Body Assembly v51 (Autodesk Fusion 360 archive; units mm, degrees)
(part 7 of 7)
sketch "Sketch1" plane through (0, 0, 0) normal (0, 0, 1) x axis (1, 0, 0)
  line L1 (-7.25, -8.75) -> (7.25, -8.75)
  line L2 (-7.25, 8.75) -> (-7.25, -8.75)
  line L3 (7.25, 8.75) -> (-7.25, 8.75)
  line L4 (7.25, -8.75) -> (7.25, 8.75)
  line L5 (-7.25, 8.75) -> (7.25, -8.75)
  line L6 (7.25, 8.75) -> (-7.25, -8.75)
  line L7 (0, 8.75) -> (0, -8.75)
  line L8 (-2.5, -2.35) -> (2.5, -2.35)
  line L9 (-2.5, 1.45) -> (-2.5, -2.35)
  line L10 (2.5, 1.45) -> (-2.5, 1.45)
  line L11 (2.5, -2.35) -> (2.5, 1.45)
  line L12 (-2.5, 1.45) -> (2.5, -2.35)
  line L13 (2.5, 1.45) -> (-2.5, -2.35)
  line L14 (7.25, -0.45) -> (-7.25, -0.45)
  line L15 (3.75, -8.75) -> (7.25, -5.25)
  line L16 (-3.75, -8.75) -> (-7.25, -5.25)
  arc A1 centre (0, 0.1797) radius 8.5703 clockwise from (-7.25, 4.75) to (7.25, 4.75)
  circle C1 centre (6, -0.45) radius 1.5
  circle C2 centre (-6, -0.45) radius 1.5
  point P6 (0, 0)
  point P1 (0, 0)
  point P7 (0, -8.75)
  point P8 (0, 8.75)
  point P13 (0, -0.45)
  point P14 (-7.25, -0.45)
  point P15 (7.25, -0.45)
  point P16 (7.25, 4.75)
  point P17 (-7.25, 4.75)
  point P19 (7.25, 4.75)
  point P18 (-7.25, 4.75)
  point P21 (7.25, -5.25)
  point P22 (3.75, -8.75)
  point P23 (7.25, -5.25)
  point P24 (3.75, -8.75)
  point P25 (-7.25, -5.25)
  point P26 (-3.75, -8.75)
  point P27 (6, -0.45)
  point P2 (7.25, -8.75)
  point P5 (7.25, 8.75)
  horizontal L1
  perpendicular L1 L2
  parallel L1 L3
  parallel L2 L4
  coincident L5 P6
  coincident L6 P6
  coincident P1 P6
  midpoint L1 P7
  midpoint L3 P8
  horizontal L8
  perpendicular L8 L9
  parallel L8 L10
  parallel L9 L11
  coincident L12 P13
  coincident L13 P13
  coincident L7 P13
  coincident L2 P14
  coincident L4 P15
  perpendicular L4 L14
  coincident P13 L14
  coincident L4 P16
  symmetric L7 P16 P17
  coincident P8 A1
  tangent L3 A1
  coincident P16 P19
  coincident P17 P18
  coincident L4 P21
  coincident L1 P22
  coincident P21 P23
  coincident P22 P24
  symmetric L7 P23 P25
  symmetric L7 P24 P26
  coincident L14 P27
  symmetric L7 C1 C2
  dimension "d1_4" distance P2 P5 = 17.5
  dimension "d2_4" distance L2 L4 = 14.5
  dimension "d3_4" distance L1 L8 = 6.4
  dimension "d4_4" distance L3 L10 = 7.3
  dimension "d5_4" distance L9 L11 = 5
  dimension "d6_4" distance P5 P16 = 4
  dimension "d7_4" distance P2 P21 = 3.5
  dimension "d8_4" distance P2 P22 = 3.5
  dimension "d9_4" diameter C1 = 3
  dimension "d10_4" distance L11 P27 = 3.5 (= "2 mm + 1.5 mm")
extrude "Extrude1" new body sketch "Sketch1" profile of L1 L2 L4 L8 L9 L10 L11 A1 L15 L16 C1 C2 against normal blind 1.7 named "d11_4"
extrude "Extrude2" new body sketch "Sketch1" profile of L8 L9 L10 L11 along normal blind 1.5 named "d13_4"
sketch "Sketch2" plane through (0, 0, 0) normal (0, 0, 1) x axis (-1, 0, 0)
  line L1 (3.75, 8.75) -> (7.25, 5.25)
  line L2 (-3.75, 8.75) -> (3.75, 8.75)
  line L3 (-7.25, 5.25) -> (-3.75, 8.75)
  line L4 (-7.25, 1.2792) -> (-7.25, 5.25)
  line L5 (-7.25, -4.75) -> (-7.25, -0.3792)
  line L6 (7.25, -0.3792) -> (7.25, -4.75)
  line L7 (7.25, 5.25) -> (7.25, 1.2792)
  line L8 (2.5, -1.45) -> (-2.5, -1.45)
  line L9 (2.5, 2.35) -> (2.5, -1.45)
  line L10 (-2.5, 2.35) -> (2.5, 2.35)
  line L11 (-2.5, -1.45) -> (-2.5, 2.35)
  line L12 (2.5, 2.35) -> (-2.5, -1.45)
  line L13 (2.5, -1.45) -> (-2.5, 2.35)
  line L14 (11.5, 11.95) -> (-11.5, 11.95)
  line L15 (11.5, -11.05) -> (11.5, 11.95)
  line L16 (-11.5, -11.05) -> (11.5, -11.05)
  line L17 (-11.5, 11.95) -> (-11.5, -11.05)
  line L18 (11.5, -11.05) -> (-11.5, 11.95)
  line L19 (-11.5, -11.05) -> (11.5, 11.95)
  line L20 (8.5, 8.95) -> (-8.5, 8.95)
  line L21 (8.5, -8.05) -> (8.5, 8.95)
  line L22 (-8.5, -8.05) -> (8.5, -8.05)
  line L23 (-8.5, 8.95) -> (-8.5, -8.05)
  line L24 (8.5, -8.05) -> (-8.5, 8.95)
  line L25 (-8.5, -8.05) -> (8.5, 8.95)
  arc A1 centre (-6, 0.45) radius 1.5 clockwise from (-7.25, 1.2792) to (-7.25, -0.3792)
  arc A2 centre (0, -0.1797) radius 8.5703 clockwise from (7.25, -4.75) to (-7.25, -4.75)
  arc A3 centre (6, 0.45) radius 1.5 clockwise from (7.25, -0.3792) to (7.25, 1.2792)
  circle C1 centre (-8.5, 8.95) radius 1.5
  point P15 (-2.5, -1.45)
  point P19 (-2.5, -1.45)
  point P17 (2.5, 2.35)
  point P20 (2.5, 2.35)
  point P18 (-2.5, 2.35)
  point P21 (-2.5, 2.35)
  point P16 (2.5, -1.45)
  point P22 (2.5, -1.45)
  point P27 (0, 0.45)
  point P32 (0, 0.45)
  point P28 (-8.5, 8.95)
  point P33 (-8.5, 8.95)
  point P25 (11.5, -11.05)
  point P26 (-11.5, -11.05)
  point P24 (11.5, 11.95)
  point P29 (8.5, 8.95)
  point P31 (-8.5, -8.05)
  coincident P15 P19
  coincident P17 P20
  coincident P18 P21
  coincident P16 P22
  horizontal L14
  perpendicular L14 L15
  parallel L14 L16
  parallel L15 L17
  coincident L18 P27
  coincident L19 P27
  midpoint L12 P27
  horizontal L20
  perpendicular L20 L21
  parallel L20 L22
  parallel L21 L23
  coincident L24 P32
  coincident L25 P32
  coincident P27 P32
  coincident P28 P33
  dimension "d15_3" distance P25 P26 = 23
  dimension "d16_3" distance P24 P25 = 23
  dimension "d21_3" distance P28 P29 = 17
  dimension "d22_1" distance P28 P31 = 17
  dimension "d23_1" diameter C1 = 3
extrude "Extrude3" add sketch "Sketch2" profile of L1 L2 L3 L4 A1 L5 A2 L6 A3 L7 L8 L9 L10 L11 L14 L15 L16 L17 against normal blind 1.7 named "d17_3"
fillet "Fillet1" radius 3 named "d20_3"
extrude "Extrude4" cut sketch "Sketch2" profile of C1 against normal blind 5 named "d24_1"
work_axis "WorkAxis1" sketch "Sketch2"
circular_pattern "C-Pattern1" TotalAngle 360 named "d27_1"
copy_paste "CutPaste7"
copy_paste_bodies "CopyPasteBodies1"
component_from_bodies "Body->Comp2"
copy_paste "CutPaste1"
sketch "Sketch26" plane through (0, 0, 3.1168) normal (0, 0, 1) x axis (-1, 0, 0)
  line L1 (-17.255, -17.7958) -> (-17.255, -11.4458)
  line L2 (-3.4928, -22.1208) -> (-13.668, -22.1208)
  line L3 (0.1537, -18.4744) -> (-3.4928, -22.1208)
  line L4 (0.1537, -10.7673) -> (0.1537, -18.4744)
  line L5 (-3.4928, -7.1208) -> (0.1537, -10.7673)
  line L6 (-13.668, -7.1208) -> (-3.4928, -7.1208)
  line L7 (-10.2963, -17.1208) -> (-10.2963, -12.1208)
  line L8 (-6.4963, -17.1208) -> (-10.2963, -17.1208)
  line L9 (-6.4963, -12.1208) -> (-6.4963, -17.1208)
  line L10 (-10.2963, -12.1208) -> (-6.4963, -12.1208)
  line L11 (-6.4963, -12.1208) -> (-10.2963, -17.1208)
  line L12 (-10.2963, -12.1208) -> (-6.4963, -17.1208)
  line L13 (6.8437, -26.1208) -> (-23.6363, -26.1208)
  line L14 (6.8437, -3.1208) -> (6.8437, -26.1208)
  line L15 (-23.6363, -3.1208) -> (6.8437, -3.1208)
  line L16 (-23.6363, -26.1208) -> (-23.6363, -3.1208)
  line L17 (6.8437, -3.1208) -> (-23.6363, -26.1208)
  line L18 (-23.6363, -3.1208) -> (6.8437, -26.1208)
  line L19 (-23.8863, -26.3708) -> (-23.8863, -2.8708)
  line L20 (7.0937, -26.3708) -> (-23.8863, -26.3708)
  line L21 (7.0937, -2.8708) -> (7.0937, -26.3708)
  line L22 (-23.8863, -2.8708) -> (7.0937, -2.8708)
  line L23 (-3.6338, -9.3883) -> (-13.1588, -9.3883)
  line L24 (-3.6338, 21.6466) -> (-3.6338, -9.3883)
  line L25 (-13.1588, 21.6466) -> (-3.6338, 21.6466)
  line L26 (-13.1588, -9.3883) -> (-13.1588, 21.6466)
  line L27 (-3.6338, 21.6466) -> (-13.1588, -9.3883)
  line L28 (-13.1588, 21.6466) -> (-3.6338, -9.3883)
  line L29 (-2.7026, -22.1208) -> (-4.2901, -22.1208)
  line L30 (-2.7026, -36.2208) -> (-2.7026, -22.1208)
  line L31 (-4.2901, -36.2208) -> (-2.7026, -36.2208)
  line L32 (-4.2901, -22.1208) -> (-4.2901, -36.2208)
  line L33 (-2.7026, -36.2208) -> (-4.2901, -22.1208)
  line L34 (-4.2901, -36.2208) -> (-2.7026, -22.1208)
  line L35 (-12.5026, -24.395) -> (-14.0901, -24.395)
  line L36 (-12.5026, -33.9467) -> (-12.5026, -24.395)
  line L37 (-14.0901, -33.9467) -> (-12.5026, -33.9467)
  line L38 (-14.0901, -24.395) -> (-14.0901, -33.9467)
  line L39 (-12.5026, -33.9467) -> (-14.0901, -24.395)
  line L40 (-14.0901, -33.9467) -> (-12.5026, -24.395)
  arc A1 centre (-9.026, -14.6208) radius 8.8203 clockwise from (-13.668, -22.1208) to (-17.255, -17.7958)
  arc A2 centre (-9.026, -14.6208) radius 8.8203 clockwise from (-17.255, -11.4458) to (-13.668, -7.1208)
  circle C1 centre (-3.4963, -29.1708) radius 2.2
  arc A3 centre (-8.3963, 6.1292) radius 8.75 clockwise from (-16.55, 9.3042) to (-16.55, 2.9542)
  circle C2 centre (-13.2963, -29.1708) radius 2.2
  point P12 (-10.2963, -17.1208)
  point P15 (-10.2963, -17.1208)
  point P14 (-6.4963, -12.1208)
  point P16 (-6.4963, -12.1208)
  point P13 (-6.4963, -17.1208)
  point P17 (-6.4963, -17.1208)
  point P11 (-10.2963, -12.1208)
  point P18 (-10.2963, -12.1208)
  point P19 (-8.3963, -14.6208)
  point P24 (-8.3963, -14.6208)
  point P37 (-8.3963, 6.1292)
  point P32 (-8.3963, 6.1292)
  point P38 (-4.2901, -22.1208)
  point P42 (-3.4963, -29.1708)
  point P25 (-3.4963, -29.1708)
  point P48 (-13.2963, -29.1708)
  point P43 (-13.2963, -29.1708)
  point P21 (6.8437, -26.1208)
  point P22 (6.8437, -3.1208)
  point P20 (-23.6363, -26.1208)
  point P33 (-13.1588, -9.3883)
  point P34 (-3.6338, -9.3883)
  point P46 (-12.5026, -33.9467)
  point P47 (-14.0901, -33.9467)
  point P40 (-2.7026, -36.2208)
  point P41 (-4.2901, -36.2208)
  coincident P12 P15
  coincident P14 P16
  coincident P13 P17
  coincident P11 P18
  midpoint L12 P19
  horizontal L13
  perpendicular L13 L14
  parallel L13 L15
  parallel L14 L16
  coincident L17 P24
  coincident L18 P24
  coincident P19 P24
  horizontal L23
  perpendicular L23 L24
  parallel L23 L25
  parallel L24 L26
  coincident L27 P37
  coincident L28 P37
  coincident P32 P37
  horizontal L29
  perpendicular L29 L30
  parallel L29 L31
  parallel L30 L32
  coincident L2 P38
  coincident L33 P42
  coincident L34 P42
  coincident P25 P42
  horizontal L35
  perpendicular L35 L36
  parallel L35 L37
  parallel L36 L38
  coincident L39 P48
  coincident L40 P48
  coincident P43 P48
  dimension "d229" distance P21 P22 = 23
  dimension "d230" distance P20 P21 = 30.48
  dimension "d231" = 0.25
  dimension "d232" distance P33 P34 = 9.525
  dimension "d235" distance P46 P47 = 1.5875 (= "( 1 / 16 ) * 1 in")
  dimension "d236" distance P40 P41 = 1.5875 (= "( 1 / 16 ) * 1 in")
extrude "Extrude1" cut sketch "Sketch26" profile of L1 A1 L2 L3 L4 L5 L6 A2 C1 L19 L20 L21 L22 A3 L23 L24 L26 L29 L30 L32 C2 L35 L36 L38 along normal blind 11.43
position "Position9"
extrude "Extrude2" add of existing geometry blind 11.938
copy_paste "CutPaste1"
copy_paste "CutPaste2"
sketch "Sketch27" plane through (0, 0, 8.3168) normal (0, 0, 1) x axis (-1, 0, 0)
  line L1 (-1.5476, 25.3604) -> (3.2149, 20.5979)
  line L2 (-15.2451, 25.3604) -> (-1.5476, 25.3604)
  line L3 (-20.0076, 20.5979) -> (-15.2451, 25.3604)
  line L4 (-20.0076, 9.3042) -> (-20.0076, 20.5979)
  line L5 (-16.55, 9.3042) -> (-20.0076, 9.3042)
  line L6 (-20.0076, 2.9542) -> (-16.55, 2.9542)
  line L7 (-20.0076, -11.4458) -> (-20.0076, 2.9542)
  line L8 (-17.255, -11.4458) -> (-20.0076, -11.4458)
  line L9 (0.1537, -10.7673) -> (-3.4928, -7.1208)
  line L10 (0.1537, -18.4744) -> (0.1537, -10.7673)
  line L11 (-3.4928, -22.1208) -> (0.1537, -18.4744)
  line L12 (-20.0076, -17.7958) -> (-17.255, -17.7958)
  line L13 (-20.0076, -29.3396) -> (-20.0076, -17.7958)
  line L14 (-15.2451, -34.1021) -> (-20.0076, -29.3396)
  line L15 (-1.5476, -34.1021) -> (-15.2451, -34.1021)
  line L16 (3.2149, -29.3396) -> (-1.5476, -34.1021)
  line L17 (3.2149, 20.5979) -> (3.2149, -29.3396)
  line L18 (-16.55, 2.9542) -> (-16.55, 9.3042)
  line L19 (10.3682, 15.8479) -> (-27.1608, 15.8479)
  line L20 (10.3682, -3.5896) -> (10.3682, 15.8479)
  line L21 (-27.1608, -3.5896) -> (10.3682, -3.5896)
  line L22 (-27.1608, 15.8479) -> (-27.1608, -3.5896)
  line L23 (10.3682, -3.5896) -> (-27.1608, 15.8479)
  line L24 (-27.1608, -3.5896) -> (10.3682, 15.8479)
  line L25 (-22.7793, 18.2292) -> (-24.2215, 18.2292)
  line L26 (-8.8375, 18.2292) -> (-22.7793, 18.2292)
  arc A1 centre (-8.3963, 6.1292) radius 8.75 clockwise from (-16.55, 9.3042) to (-16.55, 2.9542)
  arc A2 centre (-9.026, -14.6208) radius 8.8203 clockwise from (-17.255, -11.4458) to (-13.668, -7.1208)
  arc A3 centre (-8.5804, -15.3408) radius 9.6671 clockwise from (-13.668, -7.1208) to (-3.4928, -7.1208)
  arc A4 centre (-8.5804, -13.9008) radius 9.6671 clockwise from (-3.4928, -22.1208) to (-13.668, -22.1208)
  arc A5 centre (-9.026, -14.6208) radius 8.8203 clockwise from (-13.668, -22.1208) to (-17.255, -17.7958)
  circle C1 centre (-13.2963, 20.4292) radius 2.2
  circle C2 centre (-13.2963, -29.1708) radius 2.2
  circle C3 centre (-3.4963, 20.4292) radius 2.2
  circle C4 centre (-3.4963, -29.1708) radius 2.2
  arc A6 centre (-8.3963, 6.1292) radius 8.75 clockwise from (-16.55, 9.3042) to (-16.55, 2.9542)
  circle C5 centre (-13.2963, 20.4292) radius 2.2
  point P39 (-8.3963, 6.1292)
  point P34 (-8.3963, 6.1292)
  horizontal L19
  perpendicular L19 L20
  parallel L19 L21
  parallel L20 L22
  coincident L23 P39
  coincident L24 P39
  coincident P34 P39
  perpendicular L4 L25
  perpendicular L4 L26
  tangent C1 L26
  dimension "d239" distance L19 L26 = 2.3813 (= "( 3 / 32 ) * 1 in")
extrude "Extrude12" cut sketch "Sketch27" profile of L4 L5 A1 L6 L7 L17 L18 L19 L21 L22 against normal blind 7.3152
extrude "Extrude13" add of existing geometry blind 2.7525
extrude "Extrude14" add of existing geometry blind 7.62
sketch "Sketch28" plane through (0, 0, 8.3168) normal (0, 0, 1) x axis (-1, 0, 0)
  line L1 (-13.1588, -1.2112) -> (-13.1588, -2.8708)
  line L2 (-20.0076, 2.9542) -> (-16.55, 2.9542)
  line L3 (-20.0076, -2.8708) -> (-20.0076, 2.9542)
  line L4 (-13.1588, -2.8708) -> (-20.0076, -2.8708)
  line L5 (-27.1608, -3.5896) -> (10.3682, -3.5896)
  line L6 (-27.1608, 15.8479) -> (-27.1608, -3.5896)
  line L7 (10.3682, -3.5896) -> (10.3682, 15.8479)
  line L8 (10.3682, 15.8479) -> (-27.1608, 15.8479)
  arc A1 centre (-8.3963, 6.1292) radius 8.75 clockwise from (-13.1588, -1.2112) to (-16.55, 2.9542)
extrude "Extrude3" cut sketch "Sketch28" against normal blind 7.3152
extrude "Extrude4" add of existing geometry blind 7.62
move "Move1"
move "Move1"
extrude "Extrude5" cut of existing geometry blind -0.3036 (= "-( 0.105700787401575 in - ( ( 3 / 32 ) * 1 in ) )")
extrude "Extrude6" add of existing geometry blind 3.175
extrude "Extrude7" add of existing geometry blind 3.175
position "Position10"
sketch "Sketch29" plane through (0, 0, -2.477) normal (0, 0, 1) x axis (-1, 0, 0)
  line L1 (-20.0076, -3.5896) -> (-20.0076, 15.8479)
  line L2 (3.2149, -3.5896) -> (-20.0076, -3.5896)
  line L3 (3.2149, 15.8479) -> (3.2149, -3.5896)
  line L4 (-20.0076, 15.8479) -> (3.2149, 15.8479)
  line L5 (0.8337, 15.8479) -> (3.2149, 15.8479)
  line L6 (0.8337, -3.5896) -> (0.8337, 15.8479)
  line L7 (3.2149, -3.5896) -> (0.8337, -3.5896)
  line L8 (3.2149, 15.8479) -> (3.2149, -3.5896)
  point P8 (0.8337, -3.5896)
  point P5 (3.2149, 15.8479)
  point P6 (3.2149, 15.8479)
  horizontal L5
  vertical L6
  horizontal L7
  vertical L8
  coincident L2 P8
  coincident P5 P6
  dimension "d256" distance L6 L8 = 2.3813 (= "( 3 / 32 ) * 1 in")
extrude "Extrude8" add sketch "Sketch29" profile of L2 L3 L4 L5 L6 L7 L8 along normal blind 10.795
extrude "Extrude9" cut of existing geometry blind -0.0012 (= "-4.921E-05 in")
extrude "Extrude10" cut of existing geometry blind -0.4572
extrude "Extrude11" cut of existing geometry blind -0.25
extrude "Extrude15" add of existing geometry blind 3.175
work_plane "WorkPlane6" AlongDistance -3.175
split "Split1"
remove_body "RemoveBody1"
remove_body "RemoveBody2"
extrude "Extrude12" new body of existing geometry blind 3.175
combine "Combine1"
extrude "Extrude16" add sketch "Sketch29" profile of L2 L3 L4 L5 L6 L7 L8 along normal blind 7.62
extrude "Extrude17" cut of existing geometry blind -0.0012 (= "-4.921E-05 in")
extrude "Extrude19" add of existing geometry blind 2
sketch "Sketch30" plane through (0, 0, 3.1168) normal (0, 0, 1) x axis (-1, 0, 0)
  line L1 (0.1537, -18.4744) -> (-3.4928, -22.1208)
  line L2 (0.1537, -10.7673) -> (0.1537, -18.4744)
  line L3 (-3.4928, -7.1208) -> (0.1537, -10.7673)
  line L4 (-20.0076, -11.4458) -> (-17.255, -11.4458)
  line L5 (-20.0076, -17.7958) -> (-20.0076, -11.4458)
  line L6 (-17.255, -17.7958) -> (-20.0076, -17.7958)
  line L7 (-20.0076, -17.7958) -> (-17.255, -17.7958)
  line L8 (-17.255, -11.4458) -> (-20.0076, -11.4458)
  line L9 (-12.5772, -11.4458) -> (-20.0076, -11.4458)
  line L10 (-12.5772, -17.7958) -> (-12.5772, -11.4458)
  line L11 (-20.0076, -17.7958) -> (-12.5772, -17.7958)
  line L12 (-20.0076, -11.4458) -> (-20.0076, -17.7958)
  line L13 (-3.4928, -22.1208) -> (-13.668, -22.1208)
  line L14 (-13.668, -7.1208) -> (-3.4928, -7.1208)
  arc A1 centre (-9.026, -14.6208) radius 8.8203 clockwise from (-13.668, -22.1208) to (-17.255, -17.7958)
  arc A2 centre (-9.026, -14.6208) radius 8.8203 clockwise from (-17.255, -11.4458) to (-13.668, -7.1208)
  point P15 (-20.0076, -11.4458)
  point P17 (-20.0076, -11.4458)
  point P13 (-17.255, -17.7958)
  horizontal L9
  vertical L10
  horizontal L11
  vertical L12
  coincident P15 P17
  coincident P13 L11
extrude "Extrude2" cut sketch "Sketch30" profile of L4 L5 L6 L7 L8 L9 L10 L11 L12 along normal blind 4.7625
extrude "Extrude20" cut of existing geometry blind -1.1906 (= "( -3 / 64 ) * 1 in")
sketch "Sketch31" plane through (0, 0, -2.1734) normal (0, 0, 1) x axis (-1, 0, 0)
  line L1 (-20.0076, 15.8479) -> (2.0243, 15.8479)
  line L2 (-20.0076, -3.5896) -> (-20.0076, 15.8479)
  line L3 (2.0243, -3.5896) -> (-20.0076, -3.5896)
  line L4 (2.0243, 15.8479) -> (2.0243, -3.5896)
  line L5 (-18.8169, -3.5896) -> (-20.0076, -3.5896)
  line L6 (-18.8169, 15.8479) -> (-18.8169, -3.5896)
  line L7 (-20.0076, 15.8479) -> (-18.8169, 15.8479)
  line L8 (-20.0076, -3.5896) -> (-20.0076, 15.8479)
  line L9 (-18.8169, 15.8479) -> (-20.0076, -3.5896)
  line L10 (-18.8169, -3.5896) -> (-20.0076, 15.8479)
  line L11 (-11.6624, 9.3042) -> (-27.1621, 9.3042)
  line L12 (-11.6624, 2.9542) -> (-11.6624, 9.3042)
  line L13 (-27.1621, 2.9542) -> (-11.6624, 2.9542)
  line L14 (-27.1621, 9.3042) -> (-27.1621, 2.9542)
  line L15 (-11.6624, 2.9542) -> (-27.1621, 9.3042)
  line L16 (-27.1621, 2.9542) -> (-11.6624, 9.3042)
  point P8 (-18.8169, 15.8479)
  point P4 (-20.0076, -3.5896)
  point P6 (-20.0076, -3.5896)
  point P10 (-20.0076, -3.5896)
  point P3 (-20.0076, 15.8479)
  point P11 (-20.0076, 15.8479)
  point P12 (-19.4122, 6.1292)
  point P17 (-19.4122, 6.1292)
  point P13 (-27.1621, 9.3042)
  point P16 (-27.1621, 2.9542)
  horizontal L5
  vertical L6
  horizontal L7
  vertical L8
  coincident L1 P8
  coincident P4 P6
  coincident P4 P10
  coincident P3 P11
  coincident L10 P12
  coincident L9 P12
  horizontal L11
  perpendicular L11 L12
  parallel L11 L13
  parallel L12 L14
  coincident L15 P17
  coincident L16 P17
  coincident P12 P17
  dimension "d282" distance L6 L8 = 1.1906 (= "( 3 / 64 ) * 1 in")
  dimension "d283" distance P13 P16 = 6.35
extrude "Extrude21" add sketch "Sketch31" profile of L1 L2 L3 L5 L6 L7 L8 L11 L13 along normal blind 7.3152
extrude "Extrude12" cut of existing geometry blind -1.1906 (= "( -3 / 64 ) * 1 in")
extrude "Extrude22" cut of existing geometry blind -0.3036 (= "( ( 3 / 32 ) * 1 in ) - 0.105700787401575 in")
extrude "Extrude13" add sketch "Sketch31" profile of L1 L2 L3 L5 L6 L7 L8 L11 L13 along normal blind 7.3152 and against normal blind 1.27
extrude "Extrude14" cut of existing geometry blind -0.7112
remove_instance "RemoveInstance3"
remove_instance "RemoveInstance1"
split "Split1"
split "Split2"
remove_body "RemoveBody1"
combine "Combine2"
offset_faces "OffsetFaces1" distance -0.5
move_face "MoveFace2"
move "Move1"
sketch "Sketch32" plane through (0, 0, 28) normal (0, 0, 1) x axis (-1, 0, 0)
  line L1 (-17.6263, 14.8742) -> (-17.6263, -23.6158)
  line L2 (0.8337, 14.8742) -> (-17.6263, 14.8742)
  line L3 (0.8337, -23.6158) -> (0.8337, 14.8742)
  line L4 (-17.6263, -23.6158) -> (0.8337, -23.6158)
  line L5 (-20.0076, -29.3396) -> (-20.0076, 20.5979)
  line L6 (-15.2451, -34.1021) -> (-20.0076, -29.3396)
  line L7 (-1.5476, -34.1021) -> (-15.2451, -34.1021)
  line L8 (3.2149, -29.3396) -> (-1.5476, -34.1021)
  line L9 (3.2149, 20.5979) -> (3.2149, -29.3396)
  line L10 (-1.5476, 25.3604) -> (3.2149, 20.5979)
  line L11 (-15.2451, 25.3604) -> (-1.5476, 25.3604)
  line L12 (-20.0076, 20.5979) -> (-15.2451, 25.3604)
  circle C1 centre (-13.2963, -29.1708) radius 1.7
  circle C2 centre (-3.4963, -29.1708) radius 1.7
  circle C3 centre (-3.4963, 20.4292) radius 1.7
  circle C4 centre (-13.2963, 20.4292) radius 1.7
  circle C5 centre (-30.0348, -20.1562) radius 4
  circle C6 centre (-30.0348, -20.1562) radius 7
  concentric C5 C6
  dimension "d298" diameter C5 = 8
  dimension "d299" diameter C6 = 14
extrude "Extrude13" new body sketch "Sketch32" profile of C5 C6 along normal blind 7
align "Align2"
split "Split1"
copy_paste_bodies "CutPasteBodies3"
sketch "Sketch34" plane through (0, 0, 26.3456) normal (0, 0, -1) x axis (1, 0, 0)
  circle C1 centre (8.3963, -14.6208) radius 3.175
extrude "Extrude1" cut sketch "Sketch34" against normal blind 8.95 (magnitude of "-15.3 mm + 6.35 mm")
extrude "Extrude6" cut of existing geometry blind -2.5908
extrude "Extrude1" add of existing geometry blind 0.9906
extrude "Extrude3" add of existing geometry blind 2.9769 (= "0.0234488188976379 in + ( ( 3 / 32 ) * 1 in )")
extrude "Extrude4" cut of existing geometry blind -2.9769 (= "-( 0.0234488188976379 in + ( ( 3 / 32 ) * 1 in ) )")
position "Position11"
move "Move1"
extrude "Extrude2" cut of existing geometry blind 2.2769 (= "0.0384586614173229 in + 1.3 mm")
align "Align1"
extrude "Extrude3" cut of existing geometry blind -2.286
extrude "Extrude4" add of existing geometry blind 1.0922
extrude "Extrude7" add of existing geometry blind 1.8796
align "Align3"
extrude "Extrude5" add of existing geometry blind 0.7937 (= "( 1 / 32 ) * 1 in")
extrude "Extrude6" cut of existing geometry blind -0.7937 (= "( -1 / 32 ) * 1 in")
move "Move2"
extrude "Extrude8" cut of existing geometry blind -0.7937 (= "( -1 / 32 ) * 1 in")
extrude "Extrude5" add of existing geometry blind 0.7937 (= "( 1 / 32 ) * 1 in")
align "Align2"
extrude "Extrude6" add of existing geometry blind 0.7937 (= "( 1 / 32 ) * 1 in")
extrude "Extrude7" add of existing geometry blind 2.0066
extrude "Extrude23" add of existing geometry blind 4.445 (= "0.30 in - 0.125 in")
extrude "Extrude2" cut of existing geometry blind -4.1402
component_from_bodies "Body->Comp3"
copy_paste "CutPaste8"
sketch "Sketch35" plane through (-3.2149, 0, 0) normal (-1, 0, 0) x axis (0, -1, 0)
  line L1 (-11.4458, 5.1418) -> (-11.4458, 7.8793)
  line L2 (20.5979, 5.1418) -> (-11.4458, 5.1418)
  line L3 (20.5979, 28) -> (20.5979, 5.1418)
  line L4 (-29.3396, 28) -> (20.5979, 28)
  line L5 (-29.3396, 5.1418) -> (-29.3396, 28)
  line L6 (-17.7958, 5.1418) -> (-29.3396, 5.1418)
  line L7 (-17.7958, 7.8793) -> (-17.7958, 5.1418)
  line L8 (-11.4458, 7.8793) -> (-17.7958, 7.8793)
  line L9 (-7.6208, 17.8125) -> (-21.6208, 17.8125)
  line L10 (-7.6208, 24.8125) -> (-21.6208, 24.8125)
  line L11 (-21.6208, 17.8125) -> (-7.6208, 24.8125)
  line L12 (-21.6208, 24.8125) -> (-7.6208, 17.8125)
  circle C1 centre (-14.6208, 21.3125) radius 3.5
  point P13 (-7.6208, 24.8125)
  point P14 (-7.6208, 24.8125)
  point P10 (-21.6208, 17.8125)
  point P15 (-21.6208, 17.8125)
  point P11 (-7.6208, 17.8125)
  point P16 (-7.6208, 17.8125)
  point P12 (-21.6208, 24.8125)
  point P17 (-21.6208, 24.8125)
  point P18 (-14.6208, 21.3125)
  coincident P13 P14
  coincident P10 P15
  coincident P11 P16
  coincident P12 P17
  midpoint L11 P18
  dimension "d336" diameter C1 = 7
sketch "Sketch37" plane through (0, 0, 17.8125) normal (0, 0, 1) x axis (-1, 0, 0)
  line L1 (0.0837, 3.7223) -> (0.0837, -22.8658)
  line L2 (-16.8763, -22.8658) -> (-16.8763, 3.7223)
  line L3 (0.0837, -22.8658) -> (-16.8763, -22.8658)
  circle C1 centre (-8.3963, -14.6208) radius 8
  arc A1 centre (-8.3963, 5.8792) radius 8.75 clockwise from (0.0837, 3.7223) to (-16.8763, 3.7223)
  circle C2 centre (-8.3963, -14.6208) radius 8
  circle C3 centre (-8.3963, -14.6208) radius 7
  circle C4 centre (-8.3963, -14.6208) radius 7
  circle C5 centre (-8.3963, -14.6208) radius 7.2
  dimension "d345" = 0.2
extrude "Extrude14" new body sketch "Sketch37" profile of C1 L1 A1 L2 L3 C2 C5 along normal blind 8.5875
combine "Combine3"
extrude "Extrude11" cut sketch "Sketch35" profile of C1 against normal blind 35.56
sketch "Sketch38" plane through (-0.8337, 0, 0) normal (1, 0, 0) x axis (0, 1, 0)
  line L1 (-14.8742, 28) -> (23.6158, 28)
  line L2 (-14.8742, 26.4) -> (-14.8742, 28)
  line L3 (23.6158, 26.4) -> (-14.8742, 26.4)
  line L4 (23.6158, 28) -> (23.6158, 26.4)
  line L5 (18.1208, 17.8125) -> (11.1208, 17.8125)
  line L6 (18.1208, 24.8125) -> (18.1208, 17.8125)
  line L7 (11.1208, 24.8125) -> (18.1208, 24.8125)
  line L8 (11.1208, 17.8125) -> (11.1208, 24.8125)
  line L9 (18.1208, 24.8125) -> (11.1208, 17.8125)
  line L10 (11.1208, 24.8125) -> (18.1208, 17.8125)
  line L11 (22.6208, 17.8125) -> (14.6208, 17.8125)
  line L12 (21.8208, 17.8125) -> (14.6208, 17.8125)
  line L13 (18.1208, 24.8125) -> (11.1208, 24.8125)
  line L14 (18.1208, 30.6305) -> (18.1208, 24.8125)
  line L15 (11.1208, 30.6305) -> (18.1208, 30.6305)
  line L16 (11.1208, 24.8125) -> (11.1208, 30.6305)
  circle C1 centre (14.6208, 21.3125) radius 3.5
  point P11 (14.6208, 21.3125)
  point P6 (14.6208, 21.3125)
  point P14 (21.8208, 17.8125)
  point P9 (18.1208, 24.8125)
  point P7 (11.1208, 17.8125)
  point P8 (18.1208, 17.8125)
  horizontal L5
  perpendicular L5 L6
  parallel L5 L7
  parallel L6 L8
  coincident L9 P11
  coincident L10 P11
  coincident P6 P11
  coincident L5 P14
  horizontal L13
  vertical L14
  horizontal L15
  vertical L16
  coincident P9 L14
  dimension "d358" distance P7 P8 = 7
extrude "Extrude12" cut sketch "Sketch38" profile of L1 L3 C1 L5 L6 L7 L8 L11 L12 L13 L14 L15 L16 along normal blind 18.46
extrude "Extrude8" add of existing geometry blind 0.5 (= "0.5 * ( 0.1018700787401575 in - ( ( 1 / 16 ) * 1 in ) )")
extrude "Extrude9" add of existing geometry blind 0.5 (= "0.5 * ( 0.1018700787401575 in - ( ( 1 / 16 ) * 1 in ) )")
work_plane "WorkPlane8" RotateAngle 0
sketch "Sketch39" plane through (4.3963, 14.6208, 18.5259) normal (-1, 0, 0) x axis (0, 1, 0)
  circle C1 centre (0, -2.7866) radius 3.5
  circle C2 centre (0, -2.7866) radius 2
  concentric C1 C2
  dimension "d366" diameter C2 = 4
extrude "Extrude10" cut sketch "Sketch39" profile of C2 against normal blind 1.5
extrude "Extrude9" add of existing geometry blind 0.125 (= "0.25 mm / 2")
extrude "Extrude10" add of existing geometry blind 0.125 (= "0.25 mm / 2")
extrude "Extrude11" add of existing geometry blind 2.032
sketch "Sketch40" plane through (0, 0, 24.8191) normal (0, 0, 1) x axis (-1, 0, 0)
  line L1 (-7.6026, -12.7708) -> (-7.6026, -16.4708)
  line L2 (-9.1901, -12.7708) -> (-7.6026, -12.7708)
  line L3 (-9.1901, -16.4708) -> (-9.1901, -12.7708)
  line L4 (-7.6026, -16.4708) -> (-9.1901, -16.4708)
  line L5 (-7.3526, -12.5208) -> (-7.3526, -16.7208)
  line L6 (-9.4401, -12.5208) -> (-7.3526, -12.5208)
  line L7 (-9.4401, -16.7208) -> (-9.4401, -12.5208)
  line L8 (-7.3526, -16.7208) -> (-9.4401, -16.7208)
  circle C1 centre (-8.3963, -14.6208) radius 4
  dimension "d375" = 0.25
extrude "Extrude12" cut sketch "Sketch40" profile of L1 L2 L3 L4 L5 L6 L7 L8 against normal blind 12.0142
delete_face "DeleteFace8"
delete_face "DeleteFace9"
delete_face "DeleteFace5"
delete_face "DeleteFace6"
delete_face "DeleteFace10"
delete_face "DeleteFace7"
delete_face "DeleteFace11"
delete_face "DeleteFace8"
fillet "Fillet2" radius 3.175
sketch "Sketch41" plane through (0, 0, 1.968) normal (0, 0, 1) x axis (-1, 0, 0)
  line L1 (-20.0076, 9.0542) -> (-18.8169, 9.0542)
  line L2 (-20.0076, 2.7042) -> (-20.0076, 9.0542)
  line L3 (-18.8169, 2.7042) -> (-20.0076, 2.7042)
  line L4 (-18.8169, -3.8396) -> (-18.8169, 2.7042)
  line L5 (2.0243, -3.8396) -> (-18.8169, -3.8396)
  line L6 (2.0243, 15.5979) -> (2.0243, -3.8396)
  line L7 (-18.8169, 15.5979) -> (2.0243, 15.5979)
  line L8 (-18.8169, 9.0542) -> (-18.8169, 15.5979)
  line L9 (-12.9401, 2.7042) -> (-20.0076, 2.7042)
  line L10 (-12.9401, 9.0542) -> (-12.9401, 2.7042)
  line L11 (-20.0076, 9.0542) -> (-12.9401, 9.0542)
  line L12 (-20.0076, 2.7042) -> (-20.0076, 9.0542)
  circle C1 centre (-8.3963, 5.8792) radius 8.75
  circle C2 centre (-8.3963, 5.8792) radius 8.75
  point P4 (-20.0076, 2.7042)
  point P11 (-20.0076, 2.7042)
  point P3 (-20.0076, 9.0542)
  point P14 (-20.0076, 9.0542)
  horizontal L9
  vertical L10
  horizontal L11
  vertical L12
  coincident P4 P11
  coincident P3 P14
extrude "Extrude24" add sketch "Sketch41" profile of L4 L5 L6 L7 L8 C1 C2 L9 L11 along normal blind 3.1738
extrude "Extrude13" cut of existing geometry blind -1
extrude "Extrude13" add of existing geometry blind 2.7375
as_built_joint "As-built2"
remove_instance "RemoveInstance3"
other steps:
base_feature "Base Feature1"
base_feature "Base Feature1"
base_feature "Base Feature1"
base_feature "Base Feature1"
base_feature "Base Feature1"
base_feature "Base Feature1"
base_feature "Base Feature1"
base_feature "Base Feature1"
base_feature "Base Feature1"
base_feature "Base Feature2"
move "Move1"
base_feature "Base Feature1"
base_feature "Base Feature3"
move "Move2"
base_feature "Base Feature2"
base_feature "Base Feature2"
move "Move1"
base_feature "Base Feature4"
base_feature "Base Feature3"
move "Move2"
base_feature "Base Feature1"
delete_face "DeleteFace5"
delete_face "DeleteFace6"
delete_face "DeleteFace7"
offset_faces "OffsetFaces1" distance -3.175
chamfer "Chamfer1" distance 4.7625
move_face "MoveFace1"
base_feature "Base Feature1"
fillet "Fillet1" radius 3.175
create_component "CreateComponent1"
create_component "CreateComponent2"
create_component "CreateComponent1"
create_component "CreateComponent1"
create_component "CreateComponent2"
create_component "CreateComponent2"
remove_body "RemoveBody1"
remove_body "RemoveBody1"
remove_body "RemoveBody2"
create_component "CreateComponent3"
remove_body "RemoveBody1"
create_component "CreateComponent3"
remove_body "RemoveBody3"
remove_instance "RemoveInstance1"
create_component "CreateComponent4"
remove_instance "RemoveInstance2"
remove_body "RemoveBody1"
remove_body "RemoveBody4"
create_component "CreateComponent1"
remove_body "RemoveBody2"
remove_body "RemoveBody3"
remove_body "RemoveBody4"
remove_body "RemoveBody6"
remove_instance "RemoveInstance1"
remove_body "RemoveBody7"
remove_body "RemoveBody9"
remove_instance "RemoveInstance1"
remove_body "RemoveBody5"
remove_body "RemoveBody6"
remove_body "RemoveBody1"
remove_body "RemoveBody2"
create_component "CreateComponent5"
remove_instance "RemoveInstance3"
create_component "CreateComponent1"
create_component "CreateComponent2"
create_component "CreateComponent3"
create_component "CreateComponent4"
create_component "CreateComponent5"
create_component "CreateComponent6"
create_component "CreateComponent6"
remove_instance "RemoveInstance1"
create_component "CreateComponent1"
remove_body "RemoveBody5"
create_component "CreateComponent2"
remove_body "RemoveBody6"
create_component "CreateComponent3"
remove_body "RemoveBody7"
create_component "CreateComponent7"
remove_instance "RemoveInstance5"
remove_instance "RemoveInstance2"
create_component "CreateComponent26"
remove_instance "RemoveInstance9"
create_component "CreateComponent27"
remove_body "RemoveBody10"
remove_instance "RemoveInstance10"
create_component "CreateComponent28"
remove_instance "RemoveInstance11"
remove_instance "RemoveInstance12"
remove_body "RemoveBody11"
remove_body "RemoveBody1"
create_component "CreateComponent48"
remove_body "RemoveBody13"
remove_instance "RemoveInstance13"
remove_body "RemoveBody14"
